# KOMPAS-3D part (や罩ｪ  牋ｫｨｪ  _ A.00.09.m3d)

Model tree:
1. Эскиз:1
2. Операция выдавливания:1
     Расстояние 1 = 36; Расстояние 2 = 36
3. Фаска:1
     Угол = 45; Длина 1 = 1; Длина 2 = 1
4. Отверстие:1
     Глубина выреза = 15; Диаметр отверстия = 6.64684; Угол конуса торца = 180; Диаметр зенковки = 8.5; Глубина зенковки = 0.926582; Угол зенковки = 90
5. M8
     Длина резьбы = 15; Шаг резьбы = 1.25; Номинальный диаметр резьбы = 8
6. Зеркальный массив:1
7. Экземпляр ( 1 )
8. Экземпляр ( 2 )  (with: Отверстие:1)

Referenced files in C:\Program Files (x86)\ASCON\KOMPAS-3D V15\Sys\Thread\: cil1_24705-2004.xml
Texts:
  Сталь 20  ГОСТ 1050-88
